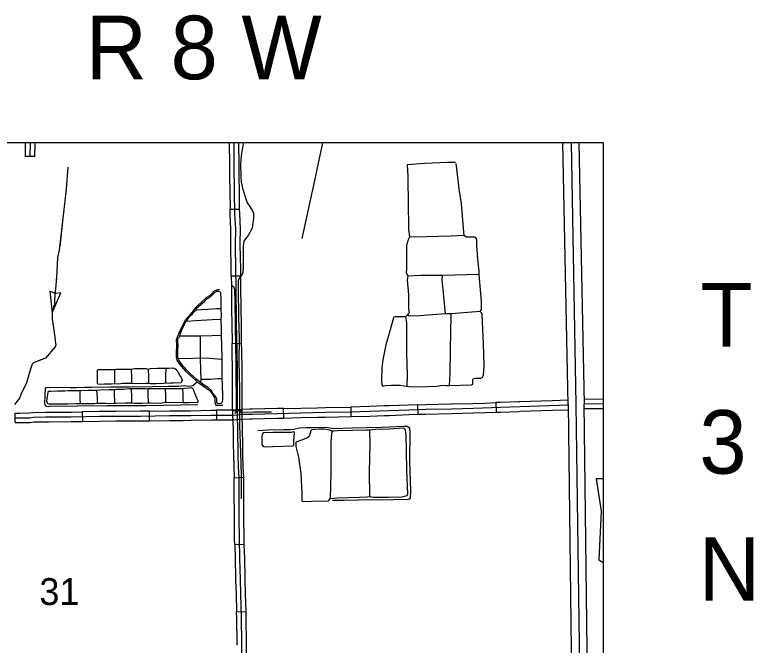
# Model space of a CAD drawing. Extents: x 1127717 to 1741049, y 2026793 to 2244711.
# Drawn here: x 1340378 to 1351991, y 2104033 to 2113957 of the extents above; entities that cross this region are included whole.
import ezdxf

# ---------------------------------------------------------------- set-up
doc = ezdxf.new("R2010")
doc.units = 0
for name, color, linetype in [('1', 7, 'Continuous'), ('10', 7, 'Continuous'), ('21', 7, 'Continuous'), ('31', 7, 'Continuous'), ('32', 7, 'Continuous'), ('35', 7, 'Continuous'), ('43', 7, 'Continuous'), ('5', 7, 'Continuous'), ('R_Draft', 7, 'Continuous')]:
    doc.layers.add(name, color=color, linetype=linetype)

msp = doc.modelspace()

# ---------------------------------------------------------------- linework, layer by layer
at = {"layer": '1'}
msp.add_lwpolyline([(1349634, 2111942), (1278363, 2111942), (1278363, 2066677), (1349634, 2066677)], close=True, dxfattribs=at)
at = {"layer": '10'}
for points in [[(1349083, 2107824), (1348999, 2111942)], [(1349249, 2111942), (1349333, 2107829)], [(1349083, 2107825), (1349139, 2103107), (1349131, 2102977), (1349132, 2102917), (1349088, 2102686), (1349055, 2102567), (1348665, 2101424), (1348636, 2101355), (1348589, 2101174), (1348562, 2101044), (1348543, 2100919), (1348488, 2100640), (1348422, 2100058), (1348397, 2099908), (1348222, 2099276), (1348167, 2098972), (1348173, 2098815), (1348192, 2096871), (1348174, 2095757), (1348169, 2095037), (1348170, 2094676)], [(1348420, 2094677), (1348419, 2095037), (1348423, 2095754), (1348442, 2096871), (1348423, 2098821), (1348418, 2098954), (1348466, 2099220), (1348641, 2099853), (1348670, 2100023), (1348736, 2100602), (1348789, 2100877), (1348808, 2101000), (1348832, 2101116), (1348874, 2101276), (1348899, 2101337), (1349294, 2102493), (1349332, 2102629), (1349382, 2102895), (1349381, 2102971), (1349389, 2103101), (1349333, 2107828)]]:
    msp.add_lwpolyline(points, dxfattribs=at)
at = {"layer": '21'}
msp.add_lwpolyline([(1349634, 2106653), (1349522, 2106653), (1349598, 2106146), (1349564, 2105376), (1349632, 2105333), (1349634, 2105333)], dxfattribs=at)
at = {"layer": '31'}
for p, q in [((1343764, 2110895), (1343914, 2110898)), ((1343933, 2109841), (1343783, 2109840)), ((1343933, 2109841), (1343933, 2109841)), ((1343796, 2108784), (1343946, 2108786)), ((1346720, 2107668), (1346716, 2107818)), ((1347945, 2107852), (1347950, 2107702)), ((1349085, 2107740), (1349080, 2107889)), ((1340385, 2107537), (1340384, 2107687)), ((1341439, 2107707), (1341441, 2107557)), ((1342497, 2107568), (1342495, 2107718)), ((1343552, 2107732), (1343552, 2107582)), ((1343804, 2107729), (1343954, 2107729)), ((1343954, 2107729), (1343804, 2107729)), ((1344609, 2107609), (1344605, 2107759)), ((1345661, 2107782), (1345665, 2107632)), ((1345661, 2107782), (1345661, 2107782)), ((1342497, 2107568), (1342497, 2107568)), ((1344609, 2107609), (1344609, 2107609)), ((1343830, 2106670), (1343980, 2106677)), ((1343987, 2105620), (1343837, 2105615)), ((1343866, 2104560), (1344016, 2104564))]:
    msp.add_line(p, q, dxfattribs=at)
for points in [[(1343752, 2111942), (1343756, 2111598), (1343757, 2111424)], [(1343879, 2107659), (1343879, 2107985), (1343879, 2108345), (1343873, 2108679), (1343867, 2109098), (1343859, 2109694), (1343857, 2109952), (1343849, 2110336), (1343853, 2110582), (1343841, 2110825), (1343835, 2111166), (1343831, 2111599), (1343827, 2111942)], [(1343907, 2111425), (1343906, 2111599), (1343902, 2111942)], [(1343757, 2111424), (1343760, 2111165), (1343764, 2110895)], [(1343914, 2110898), (1343910, 2111167), (1343907, 2111425)], [(1343774, 2110370), (1343778, 2110581), (1343766, 2110823), (1343764, 2110895)], [(1343924, 2110368), (1343928, 2110583), (1343916, 2110828), (1343914, 2110898)], [(1343783, 2109840), (1343782, 2109950), (1343774, 2110336), (1343774, 2110370)], [(1343933, 2109841), (1343932, 2109953), (1343924, 2110336), (1343924, 2110368)], [(1343783, 2109840), (1343784, 2109693), (1343789, 2109312)], [(1343939, 2109314), (1343934, 2109694), (1343933, 2109841)], [(1343789, 2109312), (1343792, 2109097), (1343796, 2108784)], [(1343946, 2108786), (1343942, 2109099), (1343939, 2109314)], [(1343804, 2108257), (1343804, 2108344), (1343798, 2108678), (1343796, 2108784)], [(1343954, 2108257), (1343954, 2108345), (1343948, 2108680), (1343946, 2108786)], [(1343804, 2107729), (1343804, 2107985), (1343804, 2108257)], [(1343954, 2107729), (1343954, 2107985), (1343954, 2108257)], [(1343877, 2107662), (1343950, 2107668), (1344112, 2107673), (1344510, 2107682), (1344877, 2107691), (1345264, 2107700), (1345659, 2107707), (1345959, 2107716), (1346267, 2107727), (1346574, 2107739), (1346841, 2107747), (1347245, 2107756), (1347591, 2107765), (1348014, 2107779), (1348325, 2107790), (1349083, 2107815)], [(1346188, 2107799), (1345956, 2107791), (1345661, 2107782)], [(1346716, 2107818), (1346571, 2107814), (1346264, 2107802), (1346188, 2107799)], [(1346716, 2107818), (1346839, 2107822), (1347243, 2107831), (1347244, 2107831)], [(1347244, 2107831), (1347588, 2107840), (1347771, 2107846)], [(1347771, 2107846), (1347945, 2107852)], [(1348299, 2107864), (1348011, 2107854), (1347945, 2107852)], [(1348827, 2107881), (1348323, 2107865), (1348299, 2107864)], [(1349080, 2107889), (1348827, 2107881)], [(1340384, 2107687), (1340459, 2107688), (1340605, 2107690), (1340669, 2107698), (1340859, 2107702), (1340912, 2107702)], [(1340912, 2107702), (1341264, 2107704), (1341439, 2107707)], [(1341968, 2107714), (1341708, 2107712), (1341439, 2107707)], [(1342495, 2107718), (1342353, 2107716), (1341968, 2107714)], [(1342495, 2107718), (1342818, 2107722), (1343023, 2107723)], [(1343023, 2107723), (1343144, 2107724), (1343472, 2107732), (1343552, 2107732)], [(1344077, 2107747), (1343945, 2107743), (1343871, 2107737), (1343801, 2107732), (1343644, 2107732), (1343552, 2107732)], [(1343804, 2107729), (1343804, 2107658), (1343812, 2107422), (1343815, 2107200)], [(1343965, 2107202), (1343962, 2107426), (1343954, 2107660), (1343954, 2107729)], [(1344605, 2107759), (1344508, 2107757), (1344110, 2107748), (1344077, 2107747)], [(1344605, 2107759), (1344875, 2107766), (1345133, 2107772)], [(1345133, 2107772), (1345263, 2107775), (1345658, 2107782), (1345661, 2107782)], [(1346720, 2107668), (1346842, 2107672), (1347246, 2107681), (1347248, 2107681)], [(1347248, 2107681), (1347593, 2107690), (1347777, 2107696)], [(1347777, 2107696), (1347950, 2107702)], [(1347950, 2107702), (1348016, 2107704), (1348304, 2107714)], [(1348304, 2107714), (1348328, 2107715), (1348832, 2107731)], [(1348832, 2107731), (1349085, 2107740)], [(1340385, 2107612), (1340459, 2107613), (1340610, 2107615), (1340675, 2107623), (1340860, 2107627), (1341265, 2107629), (1341709, 2107637), (1342354, 2107641), (1342819, 2107647), (1343145, 2107649), (1343473, 2107657), (1343644, 2107657), (1343803, 2107657), (1343877, 2107662)], [(1341441, 2107557), (1341710, 2107562), (1341968, 2107564)], [(1341968, 2107564), (1342354, 2107566), (1342497, 2107568)], [(1342497, 2107568), (1342819, 2107572), (1343024, 2107573)], [(1343024, 2107573), (1343146, 2107574), (1343474, 2107582), (1343552, 2107582)], [(1343552, 2107582), (1343644, 2107582), (1343805, 2107582), (1343882, 2107587), (1343954, 2107593), (1344082, 2107597)], [(1343973, 2102450), (1343970, 2102615), (1343966, 2102850), (1343960, 2103193), (1343954, 2103543), (1343948, 2104064), (1343944, 2104461), (1343934, 2104844), (1343926, 2105067), (1343920, 2105402), (1343910, 2105706), (1343908, 2106026), (1343905, 2106364), (1343905, 2106658), (1343897, 2106842), (1343891, 2107039), (1343887, 2107424), (1343879, 2107659)], [(1344082, 2107597), (1344114, 2107598), (1344511, 2107607), (1344609, 2107609)], [(1344609, 2107609), (1344879, 2107616), (1345137, 2107622)], [(1345137, 2107622), (1345266, 2107625), (1345661, 2107632), (1345665, 2107632)], [(1345665, 2107632), (1345961, 2107641), (1346193, 2107649)], [(1346193, 2107649), (1346270, 2107652), (1346576, 2107664), (1346720, 2107668)], [(1340385, 2107537), (1340460, 2107538), (1340616, 2107540), (1340680, 2107548), (1340861, 2107552), (1340912, 2107552)], [(1340912, 2107552), (1341265, 2107554), (1341441, 2107557)], [(1343815, 2107200), (1343816, 2107038), (1343822, 2106839), (1343830, 2106670)], [(1343980, 2106677), (1343972, 2106845), (1343966, 2107041), (1343965, 2107202)], [(1343832, 2106145), (1343830, 2106364), (1343830, 2106657), (1343830, 2106670)], [(1343982, 2106146), (1343980, 2106365), (1343980, 2106660), (1343980, 2106677)], [(1343837, 2105615), (1343835, 2105704), (1343833, 2106026), (1343832, 2106145)], [(1343987, 2105620), (1343985, 2105707), (1343983, 2106027), (1343982, 2106146)], [(1343837, 2105615), (1343845, 2105400), (1343850, 2105088)], [(1344000, 2105091), (1343995, 2105404), (1343987, 2105620)], [(1343850, 2105088), (1343851, 2105065), (1343859, 2104841), (1343866, 2104560)], [(1344016, 2104564), (1344009, 2104846), (1344001, 2105069), (1344000, 2105091)], [(1343873, 2104033), (1343873, 2104064), (1343869, 2104460), (1343866, 2104560)], [(1344023, 2104035), (1344023, 2104065), (1344019, 2104462), (1344016, 2104564)], [(1344029, 2103507), (1344029, 2103544), (1344023, 2104035)]]:
    msp.add_lwpolyline(points, dxfattribs=at)
at = {"layer": '32'}
msp.add_line((1340696, 2111724), (1340546, 2111726), dxfattribs=at)
for points in [[(1340546, 2111726), (1340549, 2111942)], [(1340621, 2111725), (1340624, 2111942), (1340624, 2111942)], [(1340696, 2111724), (1340699, 2111941), (1340699, 2111942)], [(1349634, 2107906), (1349332, 2107902)], [(1349634, 2107831), (1349333, 2107827)], [(1349634, 2107756), (1349334, 2107752)]]:
    msp.add_lwpolyline(points, dxfattribs=at)
at = {"layer": '35'}
for points in [[(1347309, 2111630), (1347178, 2111634), (1346827, 2111616), (1346551, 2111596)], [(1346551, 2111596), (1346558, 2111416), (1346566, 2110943), (1346569, 2110661), (1346572, 2110574), (1346580, 2110505), (1346585, 2110458), (1346563, 2110414), (1346539, 2110328), (1346538, 2110247), (1346539, 2110120), (1346539, 2109945), (1346535, 2109900), (1346558, 2109842), (1346549, 2109780), (1346569, 2109554), (1346572, 2109335), (1346580, 2109266), (1346521, 2109201), (1346360, 2109201), (1346341, 2109198), (1346336, 2109188), (1346299, 2109056), (1346254, 2108906), (1346212, 2108764), (1346166, 2108526), (1346151, 2108398), (1346146, 2108191), (1346149, 2108135), (1346162, 2108113), (1346202, 2108119), (1346302, 2108127), (1346444, 2108125), (1346503, 2108114), (1346544, 2108113), (1346617, 2108100), (1346867, 2108105), (1347011, 2108111), (1347098, 2108125), (1347159, 2108124), (1347217, 2108124), (1347563, 2108133), (1347582, 2108144), (1347583, 2108210), (1347594, 2108231), (1347622, 2108238), (1347709, 2108238), (1347734, 2108250), (1347747, 2108291), (1347758, 2108427), (1347747, 2108784), (1347733, 2109118), (1347726, 2109251), (1347717, 2109263), (1347698, 2109287), (1347720, 2109318), (1347716, 2109448), (1347681, 2109871), (1347680, 2109918), (1347662, 2110109), (1347647, 2110338), (1347644, 2110421), (1347628, 2110446), (1347608, 2110455), (1347563, 2110455), (1347478, 2110457), (1347447, 2110483), (1347436, 2110597), (1347402, 2110984), (1347368, 2111210), (1347330, 2111535), (1347322, 2111616)], [(1347447, 2110483), (1347238, 2110472), (1346859, 2110460), (1346585, 2110458)], [(1347681, 2109871), (1347104, 2109855), (1346764, 2109852), (1346558, 2109842)], [(1347152, 2109251), (1347124, 2109528), (1347101, 2109779), (1347104, 2109855)], [(1343630, 2107845), (1343616, 2107838), (1343575, 2107834), (1343559, 2107841), (1343555, 2107859), (1343554, 2107910), (1343539, 2107943), (1343492, 2108003), (1343467, 2108048), (1343418, 2108090), (1343356, 2108129), (1343293, 2108175), (1343228, 2108229), (1343104, 2108341), (1343027, 2108425), (1342976, 2108492), (1342961, 2108510), (1342950, 2108546), (1342941, 2108575), (1342945, 2108682), (1342949, 2108746), (1342940, 2108827), (1342943, 2108855), (1342950, 2108870), (1342961, 2108879), (1342974, 2108897), (1342985, 2108939), (1343012, 2109008), (1343052, 2109091), (1343059, 2109107), (1343075, 2109127), (1343092, 2109163), (1343132, 2109211), (1343173, 2109249), (1343195, 2109279), (1343233, 2109312), (1343238, 2109337), (1343305, 2109399), (1343363, 2109446), (1343400, 2109486), (1343441, 2109506), (1343487, 2109551), (1343537, 2109597), (1343565, 2109609), (1343584, 2109609), (1343604, 2109600), (1343613, 2109582), (1343619, 2109488), (1343617, 2109332), (1343624, 2109216), (1343621, 2109160), (1343624, 2109004), (1343626, 2108908), (1343628, 2108747), (1343633, 2108565), (1343632, 2108531), (1343635, 2108390), (1343637, 2108269), (1343635, 2108231), (1343642, 2108131), (1343644, 2107950), (1343644, 2107897), (1343639, 2107865), (1343636, 2107852), (1343630, 2107845)], [(1343233, 2109312), (1343411, 2109323), (1343546, 2109332), (1343617, 2109332)], [(1346521, 2109201), (1346536, 2109109), (1346541, 2108639), (1346551, 2108278), (1346544, 2108113)], [(1347698, 2109287), (1347240, 2109251), (1347152, 2109251), (1346743, 2109217), (1346581, 2109214), (1346551, 2109235)], [(1347217, 2108124), (1347224, 2108310), (1347229, 2108667), (1347237, 2108981), (1347240, 2109198), (1347240, 2109251)], [(1343621, 2109160), (1343481, 2109156), (1343224, 2109138), (1343075, 2109127)], [(1343626, 2108908), (1343476, 2108903), (1343293, 2108900), (1343101, 2108898), (1342974, 2108897)], [(1343293, 2108900), (1343296, 2108720), (1343295, 2108551), (1343300, 2108361), (1343305, 2108220), (1343305, 2108200), (1343293, 2108175)], [(1343632, 2108531), (1343438, 2108546), (1343295, 2108551), (1343081, 2108542), (1342950, 2108546)], [(1343011, 2108206), (1342995, 2108162), (1342875, 2108159), (1342826, 2108159), (1342797, 2108155), (1342750, 2108157), (1342719, 2108155), (1342600, 2108148), (1342515, 2108148), (1342480, 2108153), (1342440, 2108153), (1342285, 2108150), (1342212, 2108153), (1342073, 2108151), (1342015, 2108144), (1341948, 2108146), (1341899, 2108140), (1341790, 2108142), (1341732, 2108139), (1341687, 2108140), (1341680, 2108159), (1341678, 2108362), (1341687, 2108371), (1341754, 2108374), (1341910, 2108376), (1341946, 2108371), (1341973, 2108378), (1342145, 2108381), (1342178, 2108381), (1342210, 2108381), (1342263, 2108389), (1342343, 2108389), (1342440, 2108389), (1342478, 2108378), (1342515, 2108391), (1342616, 2108394), (1342685, 2108394), (1342732, 2108394), (1342752, 2108394), (1342801, 2108394), (1342862, 2108398)], [(1342210, 2108381), (1342212, 2108249), (1342212, 2108153)], [(1342478, 2108378), (1342480, 2108260), (1342480, 2108153)], [(1342752, 2108394), (1342750, 2108271), (1342750, 2108157)], [(1342862, 2108398), (1342897, 2108389), (1342911, 2108381), (1342940, 2108338), (1342980, 2108271), (1342993, 2108247), (1343011, 2108206)], [(1341946, 2108371), (1341946, 2108246), (1341948, 2108146)], [(1343305, 2108220), (1343463, 2108222), (1343565, 2108231), (1343635, 2108231)], [(1343257, 2107856), (1343123, 2107849), (1343044, 2107851), (1343024, 2107851), (1342971, 2107852), (1342866, 2107851), (1342768, 2107852), (1342748, 2107852), (1342689, 2107843), (1342602, 2107840), (1342506, 2107841), (1342479, 2107841), (1342379, 2107840), (1342259, 2107838), (1342216, 2107841), (1342120, 2107841), (1341971, 2107838), (1341939, 2107838), (1341884, 2107834), (1341808, 2107836), (1341703, 2107836), (1341674, 2107836), (1341625, 2107831), (1341475, 2107832), (1341408, 2107832), (1341346, 2107831), (1341214, 2107827), (1341174, 2107829), (1340988, 2107829), (1340912, 2107829), (1340898, 2107834), (1340892, 2107843), (1340885, 2107874), (1340889, 2107914), (1340903, 2108015), (1340907, 2108026), (1340910, 2108030), (1340948, 2108034), (1341052, 2108037), (1341106, 2108037), (1341146, 2108037), (1341166, 2108037), (1341218, 2108043), (1341340, 2108043), (1341399, 2108043), (1341425, 2108044), (1341530, 2108046), (1341606, 2108046), (1341642, 2108046), (1341666, 2108048), (1341718, 2108055), (1341861, 2108057), (1341941, 2108061), (1341976, 2108064), (1342090, 2108066), (1342178, 2108075), (1342211, 2108072), (1342251, 2108073), (1342370, 2108072), (1342434, 2108073), (1342457, 2108070), (1342477, 2108072), (1342545, 2108075), (1342721, 2108075), (1342745, 2108075), (1342799, 2108075), (1342926, 2108075), (1342993, 2108073), (1343018, 2108072), (1343045, 2108079), (1343125, 2108086), (1343150, 2108088)], [(1341399, 2108043), (1341404, 2107914), (1341408, 2107832)], [(1341666, 2108048), (1341672, 2107934), (1341674, 2107836)], [(1341941, 2108061), (1341944, 2107979), (1341946, 2107876), (1341939, 2107838)], [(1342211, 2108072), (1342212, 2107936), (1342216, 2107841)], [(1342479, 2107841), (1342478, 2107983), (1342477, 2108072)], [(1342745, 2108075), (1342750, 2107945), (1342748, 2107852)], [(1343018, 2108072), (1343020, 2107992), (1343020, 2107903), (1343024, 2107851)], [(1343150, 2108088), (1343165, 2108086), (1343181, 2108072), (1343212, 2107992), (1343243, 2107918), (1343257, 2107883), (1343257, 2107856)], [(1346524, 2107425), (1346496, 2107451), (1346269, 2107433), (1346051, 2107429), (1346002, 2107423), (1345959, 2107421), (1345914, 2107416), (1345690, 2107414), (1345448, 2107408), (1345395, 2107401), (1345369, 2107403), (1345335, 2107421), (1345243, 2107433), (1345166, 2107433), (1345048, 2107425), (1345035, 2107408), (1345020, 2107348), (1345010, 2107320), (1344982, 2107296), (1344886, 2107260), (1344799, 2107229)], [(1344769, 2107247), (1344777, 2107384), (1344762, 2107393), (1344723, 2107382), (1344436, 2107380), (1344304, 2107378), (1344287, 2107376), (1344270, 2107356), (1344265, 2107326), (1344263, 2107194), (1344276, 2107175), (1344293, 2107164), (1344334, 2107157), (1344436, 2107160), (1344755, 2107171), (1344766, 2107182), (1344767, 2107206), (1344769, 2107247)], [(1344799, 2107229), (1344800, 2107161), (1344841, 2106991), (1344879, 2106734), (1344894, 2106421), (1344892, 2106306), (1344903, 2106297), (1345044, 2106300), (1345311, 2106306), (1345343, 2106342), (1345448, 2106353), (1345801, 2106362), (1345918, 2106368), (1345955, 2106374), (1346017, 2106366), (1346256, 2106364), (1346464, 2106370), (1346549, 2106389), (1346558, 2106415), (1346545, 2106785), (1346539, 2107095), (1346532, 2107341), (1346524, 2107425)], [(1345343, 2106342), (1345352, 2106747), (1345354, 2107241), (1345369, 2107403)], [(1345959, 2107421), (1345963, 2107194), (1345953, 2106764), (1345955, 2106374)]]:
    msp.add_lwpolyline(points, dxfattribs=at)
at = {"layer": '43'}
for p, q in [((1341012, 2109570), (1340928, 2109607)), ((1340928, 2109607), (1340966, 2109266)), ((1340966, 2109266), (1341104, 2109580)), ((1341104, 2109580), (1341013, 2109570))]:
    msp.add_line(p, q, dxfattribs=at)
for points in [[(1343976, 2111942), (1343971, 2111926), (1343936, 2111739), (1343929, 2111610), (1343934, 2111412), (1343938, 2111330), (1343966, 2111206), (1344034, 2110997), (1344076, 2110941), (1344118, 2110871), (1344130, 2110832), (1344130, 2110757), (1344113, 2110598), (1344053, 2110493), (1343983, 2110392), (1343969, 2110313), (1343969, 2109983), (1343964, 2109908), (1343955, 2109871), (1343903, 2109801), (1343892, 2109770), (1343892, 2109635), (1343896, 2109198), (1343906, 2108857), (1343903, 2108504), (1343910, 2108060), (1343913, 2107752), (1343913, 2107494), (1343927, 2107062), (1343938, 2106718), (1343938, 2106403), (1343941, 2106340)], [(1344899, 2110436), (1345099, 2111346), (1345222, 2111942)], [(1341214, 2111559), (1341187, 2111211), (1341152, 2110892), (1341077, 2110251), (1341052, 2110137), (1341033, 2109818), (1341005, 2109477), (1341001, 2109398), (1340985, 2109356), (1340966, 2109264), (1340968, 2109164), (1340985, 2109031), (1341008, 2108883), (1341017, 2108781), (1341026, 2108755), (1341015, 2108730), (1340864, 2108551), (1340674, 2108481), (1340650, 2108456), (1340620, 2108363), (1340555, 2108150), (1340486, 2108006), (1340451, 2107920), (1340374, 2107821)], [(1341188, 2111230), (1341187, 2111211), (1341152, 2110892), (1341145, 2110836)], [(1341130, 2110705), (1341085, 2110312)], [(1341062, 2110182), (1341052, 2110137), (1341033, 2109818), (1341031, 2109788)], [(1341020, 2109656), (1341005, 2109477), (1341001, 2109398), (1340988, 2109364)], [(1343791, 2109696), (1343817, 2109679), (1343833, 2109639), (1343837, 2109439), (1343846, 2109062), (1343848, 2108758), (1343855, 2108483), (1343855, 2108258), (1343861, 2107950), (1343859, 2107730), (1343857, 2107690), (1343835, 2107679)], [(1343598, 2109629), (1343563, 2109629), (1343505, 2109600), (1343450, 2109538), (1343392, 2109509), (1343315, 2109431), (1343218, 2109350), (1343151, 2109257), (1343056, 2109148), (1342976, 2108983), (1342925, 2108868), (1342917, 2108841), (1342919, 2108759), (1342915, 2108636), (1342915, 2108563), (1342925, 2108520), (1342968, 2108458), (1343062, 2108345), (1343157, 2108262), (1343248, 2108177), (1343414, 2108062), (1343444, 2108042), (1343486, 2107984), (1343513, 2107939), (1343527, 2107917), (1343527, 2107858), (1343541, 2107814), (1343648, 2107814)], [(1340972, 2109134), (1340985, 2109031), (1341008, 2108883), (1341017, 2108781), (1341026, 2108755), (1341021, 2108744)], [(1340940, 2108641), (1340864, 2108551), (1340788, 2108523)], [(1340788, 2108523), (1340674, 2108481), (1340650, 2108456), (1340638, 2108416)], [(1340598, 2108290), (1340555, 2108150), (1340486, 2108006), (1340452, 2107923)], [(1343256, 2107818), (1342443, 2107804), (1341827, 2107804), (1341372, 2107796), (1341031, 2107792), (1340936, 2107796), (1340898, 2107788), (1340868, 2107796), (1340855, 2107820), (1340849, 2107842), (1340859, 2108076), (1340870, 2108089), (1340918, 2108095), (1341247, 2108091), (1341346, 2108091), (1341479, 2108093), (1341590, 2108097), (1341889, 2108103), (1342182, 2108099), (1342537, 2108107), (1342794, 2108111), (1342953, 2108113), (1343050, 2108119), (1343115, 2108113), (1343180, 2108121), (1343248, 2108177)], [(1344416, 2107701), (1344141, 2107701), (1343938, 2107699), (1343913, 2107699)], [(1344200, 2107414), (1344366, 2107426), (1344609, 2107430), (1344712, 2107429), (1344767, 2107435), (1344856, 2107454), (1344968, 2107458), (1345090, 2107461), (1345285, 2107465), (1345379, 2107447), (1345689, 2107453), (1346150, 2107468), (1346496, 2107481), (1346547, 2107481), (1346583, 2107454), (1346591, 2107388), (1346587, 2106936), (1346600, 2106461), (1346598, 2106354), (1346594, 2106337), (1346565, 2106329), (1346331, 2106324), (1345777, 2106315), (1345557, 2106311), (1345375, 2106314)]]:
    msp.add_lwpolyline(points, dxfattribs=at)
at = {"layer": '5'}
for points in [[(1349209, 2107823), (1349133, 2111942)], [(1349279, 2102532), (1349209, 2107823)]]:
    msp.add_lwpolyline(points, dxfattribs=at)

# ---------------------------------------------------------------- texts
msp.add_text('31', height=422.4, dxfattribs=at).set_placement((1340766, 2104667))
at = {"layer": 'R_Draft'}
for s, p in [('R 8 W', (1341491, 2112942)), ('T', (1351162, 2108734)), ('3', (1351143, 2106734)), ('N', (1351134, 2104734))]:
    msp.add_text(s, height=1000, dxfattribs=at).set_placement(p)

doc.saveas('drawing.dxf')
